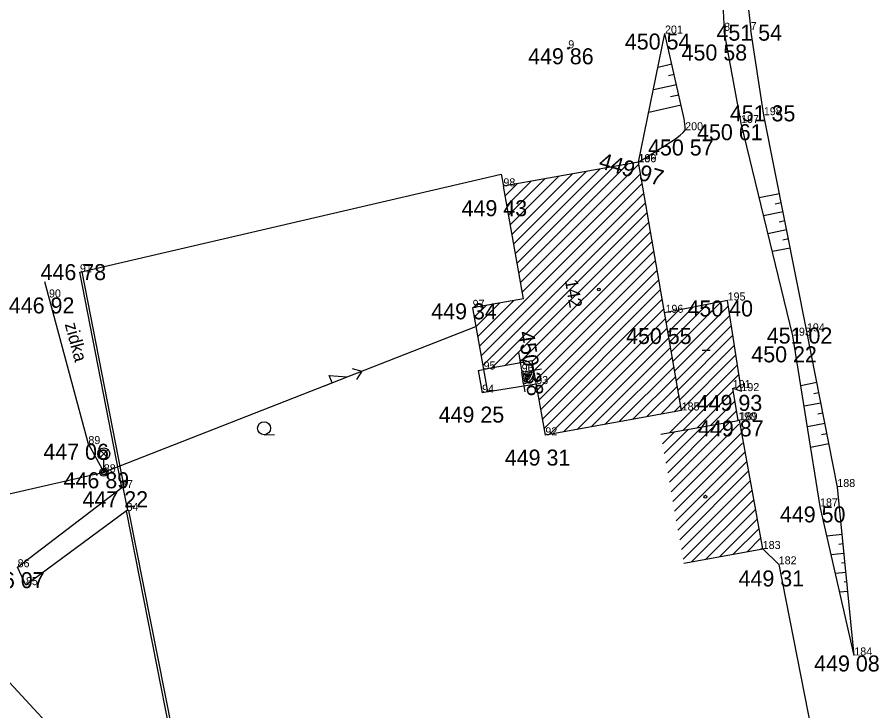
# Model space of a CAD drawing. Extents: x -559180 to -551373, y -1076947 to -1072071.
# Drawn here: x -553839.6 to -553785.8, y -1074531.9 to -1074488.6 of the extents above; entities that cross this region are included whole.
import ezdxf

# ---------------------------------------------------------------- set-up
doc = ezdxf.new("R2010")
doc.units = 0
for name, color, linetype in [('12_PLOTY', 7, 'Continuous'), ('14_BUDOVY', 7, 'Continuous'), ('17_KOMUNIKACE', 7, 'Continuous'), ('18_POLOHOPIS', 7, 'Continuous'), ('1_VODA_ZN', 7, 'Continuous'), ('20_EL_ZN', 7, 'Continuous'), ('26_SRAFY', 7, 'Continuous'), ('27_HRANA_PATA', 7, 'Continuous'), ('32', 7, 'Continuous'), ('3_BODY', 7, 'Continuous'), ('45_ZN_KULTURY', 7, 'Continuous'), ('47_ZN_STAV_OBJ$', 7, 'Continuous'), ('52_POPIS_UCELOVY', 7, 'Continuous'), ('54_C_POPISNA', 7, 'Continuous'), ('6_VYSKY', 7, 'Continuous'), ('NNnadzemní', 7, 'Continuous')]:
    doc.layers.add(name, color=color, linetype=linetype)

# ---------------------------------------------------------------- blocks, each defined once
blk = doc.blocks.new('POINT_DISPLAY')
blk.add_line((0, 0), (0, 0))
blk = doc.blocks.new('SLB')
at = {"layer": '20_EL_ZN'}
for radius in [0.25, 0.158, 0.05]:
    blk.add_circle((0, 0), radius, dxfattribs=at)
blk = doc.blocks.new('LAO')
at = {"layer": '20_EL_ZN'}
for p, q in [((-0.265, 1.415), (0.265, 0.885)), ((-0.265, 0.885), (0.265, 1.415)), ((0, 0), (0, 0.775))]:
    blk.add_line(p, q, dxfattribs=at)
blk.add_circle((0, 1.15), 0.375, dxfattribs=at)
blk = doc.blocks.new('VVH')
at = {"layer": '47_ZN_STAV_OBJ$'}
for p, q in [((-0.001, 0.746), (0, 1.246)), ((0, -0.004), (-0.001, 0.746)), ((0.1, 0.096), (0.099, 0.646)), ((0.099, 0.646), (0.5, 0.396)), ((0, -0.004), (0, 0)), ((0.1, 0.096), (0.2, 0.196)), ((0.65, 0.096), (0.1, 0.096)), ((0.399, 0.346), (0.199, 0.496)), ((0.199, 0.496), (0.2, 0.196)), ((0.2, 0.196), (0.35, 0.346)), ((0.2, 0.196), (0.5, 0.196)), ((0.5, 0.196), (0.399, 0.346)), ((0.5, 0.396), (0.65, 0.096)), ((-1.251, -0.004), (-0.751, -0.004)), ((-0.751, -0.004), (0, -0.004)), ((0.75, -0.004), (0, -0.004)), ((0.75, -0.004), (1.25, -0.004))]:
    blk.add_line(p, q, dxfattribs=at)
for start, end in [(89.9999, 179.9999), (359.9999, 89.9999)]:
    blk.add_arc((0, -0.004), 0.75, start, end, dxfattribs=at)
blk = doc.blocks.new('BZ')
at = {"layer": '47_ZN_STAV_OBJ$'}
blk.add_circle((0, 0), 0.0875, dxfattribs=at)
blk = doc.blocks.new('BD')
at = {"layer": '47_ZN_STAV_OBJ$'}
blk.add_line((-0.25, 0), (0.25, 0), dxfattribs=at)
blk = doc.blocks.new('ZAHRAD')
at = {"layer": '45_ZN_KULTURY'}
blk.add_line((0, 0), (0.65, 0.003), dxfattribs=at)
blk.add_circle((0, 0.403), 0.403, dxfattribs=at)
blk = doc.blocks.new('T')
at = {"layer": '6_VYSKY'}
blk.add_circle((0, 0), 0.05, dxfattribs=at)
blk = doc.blocks.new('ELNN')
at = {"layer": '20_EL_ZN'}
for p, q in [((0, 0), (0.5, 0)), ((0.5, 0), (0.5, 0.5)), ((0.5, 0.5), (1.5, 0)), ((1.5, 0), (2.5, 0))]:
    blk.add_line(p, q, dxfattribs=at)
blk.add_lwpolyline([(2, 0.375), (2.5, 0), (2, -0.375)], dxfattribs=at)

msp = doc.modelspace()

# ---------------------------------------------------------------- linework, layer by layer
at = {"layer": '12_PLOTY'}
for p, q in [((-553835.64, -1074504.56), (-553809.333, -1074498.431)), ((-553809.333, -1074498.431), (-553809.199, -1074499.19)), ((-553833.017, -1074517.99), (-553835.64, -1074504.56)), ((-553832.869, -1074517.961), (-553835.492, -1074504.531)), ((-553832.869, -1074517.961), (-553833.017, -1074517.99)), ((-553832.656, -1074519.446), (-553832.943, -1074517.976)), ((-553832.582, -1074519.431), (-553832.73, -1074519.46)), ((-553829.7, -1074534.8), (-553832.73, -1074519.46)), ((-553829.552, -1074534.77), (-553832.582, -1074519.43)), ((-553792.01, -1074522.8), (-553793.01, -1074521.84)), ((-553792.01, -1074522.8), (-553789.43, -1074535.85))]:
    msp.add_line(p, q, dxfattribs=at)
at = {"layer": '14_BUDOVY'}
for p, q in [((-553800.77, -1074497.69), (-553809.199, -1074499.19)), ((-553798.07, -1074513.19), (-553800.77, -1074497.69)), ((-553807.949, -1074506.216), (-553809.199, -1074499.19)), ((-553807.949, -1074506.216), (-553811.12, -1074506.78)), ((-553795.2, -1074506.32), (-553799.131, -1074507.1)), ((-553794.34, -1074511.98), (-553795.2, -1074506.32)), ((-553811.12, -1074506.78), (-553810.44, -1074510.63)), ((-553807.407, -1074510.095), (-553810.44, -1074510.63)), ((-553806.58, -1074514.74), (-553807.407, -1074510.095)), ((-553794.54, -1074513.81), (-553794.88, -1074511.79)), ((-553794.88, -1074511.79), (-553794.34, -1074511.98)), ((-553798.07, -1074513.19), (-553806.58, -1074514.74)), ((-553799.372, -1074514.675), (-553794.54, -1074513.81)), ((-553794.45, -1074513.8), (-553794.54, -1074513.81)), ((-553793.01, -1074521.84), (-553794.45, -1074513.8)), ((-553797.932, -1074522.721), (-553793.01, -1074521.84))]:
    msp.add_line(p, q, dxfattribs=at)
at = {"layer": '17_KOMUNIKACE'}
msp.add_line((-553842.61, -1074527.4), (-553837.01, -1074533.45), dxfattribs=at)
at = {"layer": '18_POLOHOPIS'}
for p, q in [((-553835.11, -1074515.29), (-553837.829, -1074505.164)), ((-553810.776, -1074510.689), (-553810.44, -1074510.63)), ((-553810.776, -1074510.689), (-553810.53, -1074512.08)), ((-553810.44, -1074510.63), (-553810.193, -1074512.026)), ((-553807.15, -1074511.54), (-553810.53, -1074512.08)), ((-553839.53, -1074522.98), (-553833.017, -1074517.99)), ((-553832.73, -1074519.46), (-553839.01, -1074524.1)), ((-553839.01, -1074524.1), (-553839.53, -1074522.98))]:
    msp.add_line(p, q, dxfattribs=at)
at = {"layer": '26_SRAFY'}
for p, q in [((-553799.539, -1074491.74), (-553798.684, -1074491.548)), ((-553798.883, -1074492.265), (-553798.54, -1074492.188)), ((-553799.829, -1074493.15), (-553798.396, -1074492.829)), ((-553798.769, -1074493.585), (-553798.253, -1074493.469)), ((-553800.119, -1074494.56), (-553798.109, -1074494.109)), ((-553793.225, -1074499.892), (-553791.965, -1074499.641)), ((-553792.224, -1074500.279), (-553791.853, -1074500.205)), ((-553792.952, -1074501.01), (-553791.741, -1074500.768)), ((-553791.985, -1074501.403), (-553791.628, -1074501.332)), ((-553792.68, -1074502.127), (-553791.516, -1074501.896)), ((-553791.746, -1074502.527), (-553791.404, -1074502.459)), ((-553792.407, -1074503.245), (-553791.292, -1074503.023)), ((-553790.628, -1074511.624), (-553789.629, -1074511.429)), ((-553789.811, -1074512.126), (-553789.504, -1074512.067)), ((-553790.424, -1074512.909), (-553789.379, -1074512.704)), ((-553789.575, -1074513.405), (-553789.255, -1074513.342)), ((-553790.221, -1074514.193), (-553789.13, -1074513.98)), ((-553789.339, -1074514.683), (-553789.005, -1074514.618)), ((-553790.017, -1074515.478), (-553788.881, -1074515.256)), ((-553789.009, -1074521.011), (-553788.053, -1074520.915)), ((-553788.258, -1074521.533), (-553787.994, -1074521.507)), ((-553788.74, -1074522.18), (-553787.934, -1074522.099)), ((-553788.094, -1074522.713), (-553787.874, -1074522.691)), ((-553788.472, -1074523.349), (-553787.815, -1074523.283)), ((-553787.93, -1074523.892), (-553787.755, -1074523.875)), ((-553788.203, -1074524.518), (-553787.695, -1074524.467))]:
    msp.add_line(p, q, dxfattribs=at)
at = {"layer": '27_HRANA_PATA'}
for p, q in [((-553794.61, -1074481.81), (-553793.76, -1074489.43)), ((-553795.74, -1074482.18), (-553795.42, -1074489.48)), ((-553794.36, -1074495.24), (-553795.42, -1074489.48)), ((-553792.94, -1074494.75), (-553793.76, -1074489.43)), ((-553800.76, -1074497.68), (-553799.11, -1074489.65)), ((-553790.25, -1074508.25), (-553792.94, -1074494.75)), ((-553791.12, -1074508.52), (-553794.36, -1074495.24)), ((-553788.35, -1074517.97), (-553790.25, -1074508.25)), ((-553789.43, -1074519.18), (-553791.12, -1074508.52)), ((-553835.11, -1074515.29), (-553834.15, -1074517.05)), ((-553787.29, -1074528.49), (-553788.35, -1074517.97)), ((-553787.29, -1074528.49), (-553789.43, -1074519.18))]:
    msp.add_line(p, q, dxfattribs=at)
for points in [[(-553797.85, -1074495.69), (-553797.849, -1074495.485), (-553797.865, -1074495.308), (-553797.915, -1074494.973), (-553799.11, -1074489.65)], [(-553800.76, -1074497.68), (-553798.58, -1074496.317), (-553798.346, -1074496.143), (-553798.157, -1074495.986), (-553797.98, -1074495.827), (-553797.85, -1074495.69)]]:
    msp.add_lwpolyline(points, dxfattribs=at)
at = {"layer": '32'}
for p, q in [((-553808.451, -1074503.392), (-553803.178, -1074498.118)), ((-553808.345, -1074503.992), (-553802.318, -1074497.965)), ((-553808.238, -1074504.593), (-553801.457, -1074497.812)), ((-553808.131, -1074505.193), (-553800.749, -1074497.811)), ((-553808.772, -1074501.591), (-553805.758, -1074498.578)), ((-553808.665, -1074502.192), (-553804.898, -1074498.425)), ((-553808.558, -1074502.792), (-553804.038, -1074498.272)), ((-553808.024, -1074505.793), (-553800.644, -1074498.413)), ((-553810.697, -1074509.174), (-553800.539, -1074499.015)), ((-553809.092, -1074499.79), (-553808.339, -1074499.037)), ((-553808.985, -1074500.391), (-553807.479, -1074498.884)), ((-553808.879, -1074500.991), (-553806.618, -1074498.731)), ((-553810.591, -1074509.774), (-553800.434, -1074499.618)), ((-553810.485, -1074510.375), (-553800.329, -1074500.22)), ((-553809.945, -1074510.543), (-553800.224, -1074500.822)), ((-553809.087, -1074510.391), (-553800.12, -1074501.424)), ((-553808.228, -1074510.24), (-553800.015, -1074502.026)), ((-553807.402, -1074510.121), (-553799.91, -1074502.629)), ((-553807.295, -1074510.721), (-553799.805, -1074503.231)), ((-553807.189, -1074511.322), (-553799.7, -1074503.833)), ((-553807.082, -1074511.922), (-553799.595, -1074504.435)), ((-553806.975, -1074512.522), (-553799.49, -1074505.037)), ((-553806.868, -1074513.122), (-553799.385, -1074505.64)), ((-553811.016, -1074507.371), (-553810.275, -1074506.63)), ((-553810.91, -1074507.972), (-553809.415, -1074506.477)), ((-553810.803, -1074508.573), (-553808.555, -1074506.324)), ((-553806.761, -1074513.723), (-553799.28, -1074506.242)), ((-553798.816, -1074508.907), (-553796.485, -1074506.575)), ((-553798.711, -1074509.509), (-553795.602, -1074506.4)), ((-553798.606, -1074510.111), (-553795.149, -1074506.654)), ((-553806.654, -1074514.323), (-553799.175, -1074506.844)), ((-553799.026, -1074507.702), (-553798.249, -1074506.925)), ((-553798.921, -1074508.304), (-553797.367, -1074506.75)), ((-553806.316, -1074514.692), (-553799.071, -1074507.446)), ((-553798.502, -1074510.713), (-553795.056, -1074507.268)), ((-553805.452, -1074514.534), (-553798.966, -1074508.048)), ((-553798.397, -1074511.315), (-553794.963, -1074507.881)), ((-553804.587, -1074514.377), (-553798.861, -1074508.651)), ((-553798.292, -1074511.918), (-553794.869, -1074508.495)), ((-553803.722, -1074514.22), (-553798.756, -1074509.253)), ((-553798.187, -1074512.52), (-553794.776, -1074509.109)), ((-553802.858, -1074514.062), (-553798.651, -1074509.855)), ((-553798.082, -1074513.122), (-553794.683, -1074509.723)), ((-553801.993, -1074513.905), (-553798.546, -1074510.457)), ((-553798.831, -1074514.578), (-553794.59, -1074510.337)), ((-553797.97, -1074514.424), (-553794.496, -1074510.951)), ((-553801.129, -1074513.747), (-553798.441, -1074511.06)), ((-553794.694, -1074511.855), (-553794.403, -1074511.565)), ((-553800.264, -1074513.59), (-553798.336, -1074511.662)), ((-553797.108, -1074514.27), (-553794.844, -1074512.005)), ((-553799.4, -1074513.432), (-553798.231, -1074512.264)), ((-553796.247, -1074514.116), (-553794.742, -1074512.61)), ((-553798.535, -1074513.275), (-553798.126, -1074512.866)), ((-553795.386, -1074513.961), (-553794.64, -1074513.216)), ((-553799.05, -1074516.474), (-553796.788, -1074514.212)), ((-553798.943, -1074517.074), (-553795.927, -1074514.058)), ((-553798.835, -1074517.674), (-553795.066, -1074513.904)), ((-553798.728, -1074518.274), (-553794.496, -1074514.042)), ((-553799.265, -1074515.275), (-553798.511, -1074514.521)), ((-553799.157, -1074515.875), (-553797.649, -1074514.367)), ((-553798.621, -1074518.873), (-553794.383, -1074514.635)), ((-553798.513, -1074519.473), (-553794.27, -1074515.229)), ((-553798.406, -1074520.073), (-553794.156, -1074515.823)), ((-553798.299, -1074520.673), (-553794.043, -1074516.417)), ((-553798.191, -1074521.272), (-553793.93, -1074517.011)), ((-553798.084, -1074521.872), (-553793.817, -1074517.605)), ((-553797.977, -1074522.472), (-553793.704, -1074518.199)), ((-553797.428, -1074522.631), (-553793.591, -1074518.793)), ((-553796.567, -1074522.477), (-553793.477, -1074519.387)), ((-553795.706, -1074522.323), (-553793.364, -1074519.981)), ((-553794.845, -1074522.168), (-553793.251, -1074520.575)), ((-553793.983, -1074522.014), (-553793.138, -1074521.169)), ((-553793.122, -1074521.86), (-553793.025, -1074521.763))]:
    msp.add_line(p, q, dxfattribs=at)
at = {"layer": 'NNnadzemní'}
for p, q in [((-553834.15, -1074517.05), (-553810.915, -1074507.941)), ((-553869.639, -1074525.168), (-553834.15, -1074517.05))]:
    msp.add_line(p, q, dxfattribs=at)

# ---------------------------------------------------------------- block references
at = {"layer": '1_VODA_ZN'}
for p in [(-553795.42, -1074489.48), (-553793.76, -1074489.43), (-553799.11, -1074489.65), (-553805.15, -1074490.57), (-553792.94, -1074494.75), (-553794.36, -1074495.24), (-553797.85, -1074495.69), (-553800.77, -1074497.69), (-553800.76, -1074497.68), (-553809.2, -1074499.19), (-553835.64, -1074504.56), (-553792.039, -1074504.633), (-553837.57, -1074506.13), (-553795.2, -1074506.32), (-553811.12, -1074506.78), (-553799.08, -1074507.09), (-553790.25, -1074508.25), (-553791.12, -1074508.52), (-553810.44, -1074510.63), (-553808.06, -1074510.79), (-553807.15, -1074511.54), (-553810.53, -1074512.08), (-553794.88, -1074511.79), (-553794.34, -1074511.98), (-553798.07, -1074513.19), (-553794.54, -1074513.81), (-553794.45, -1074513.8), (-553806.58, -1074514.74), (-553835.11, -1074515.29), (-553834.15, -1074517.05), (-553788.35, -1074517.97), (-553833.07, -1074518.03), (-553832.73, -1074519.46), (-553789.43, -1074519.18), (-553793.01, -1074521.84), (-553792.01, -1074522.8), (-553839.53, -1074522.98), (-553839.01, -1074524.1), (-553787.29, -1074528.49)]:
    msp.add_blockref('POINT_DISPLAY', p, dxfattribs=at)
at = {"layer": '20_EL_ZN', "xscale": 1.0000008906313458, "yscale": 1.0000008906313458, "rotation": 21.40698381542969}
msp.add_blockref('ELNN', (-553820.36, -1074511.644), dxfattribs=at)
at = {"layer": '20_EL_ZN'}
for name in ['LAO', 'SLB']:
    msp.add_blockref(name, (-553834.15, -1074517.05), dxfattribs=at)
at = {"layer": '32'}
for p in [(-553809.199, -1074499.19), (-553799.131, -1074507.1), (-553799.372, -1074514.675)]:
    msp.add_blockref('POINT_DISPLAY', p, dxfattribs=at)
at = {"layer": '45_ZN_KULTURY'}
msp.add_blockref('ZAHRAD', (-553824.141, -1074514.701), dxfattribs=at)
at = {"layer": '47_ZN_STAV_OBJ$'}
for name, p in [('BZ', (-553803.246, -1074505.631)), ('BD', (-553796.535, -1074509.422)), ('BZ', (-553796.589, -1074518.575))]:
    msp.add_blockref(name, p, dxfattribs=at)
at = {"layer": '47_ZN_STAV_OBJ$', "xscale": 1.0000016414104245, "yscale": 1.0000016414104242, "rotation": -81.01973074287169}
msp.add_blockref('VVH', (-553808.052, -1074510.789), dxfattribs=at)
at = {"layer": '6_VYSKY'}
msp.add_blockref('T', (-553805.15, -1074490.57), dxfattribs=at)
msp.add_blockref('T', (-553805.15, -1074490.57), dxfattribs=at)

# ---------------------------------------------------------------- texts
at = {"layer": '3_BODY'}
for s, p in [('8', (-553795.42, -1074489.48)), ('7', (-553793.76, -1074489.43)), ('201', (-553799.11, -1074489.65)), ('9', (-553805.15, -1074490.57)), ('198', (-553792.94, -1074494.75)), ('197', (-553794.36, -1074495.24)), ('200', (-553797.85, -1074495.69)), ('186', (-553800.77, -1074497.69)), ('199', (-553800.76, -1074497.68)), ('98', (-553809.2, -1074499.19)), ('91', (-553835.64, -1074504.56)), ('90', (-553837.57, -1074506.13)), ('195', (-553795.2, -1074506.32)), ('97', (-553811.12, -1074506.78)), ('196', (-553799.08, -1074507.09)), ('194', (-553790.25, -1074508.25)), ('193', (-553791.12, -1074508.52)), ('95', (-553810.44, -1074510.63)), ('96', (-553808.06, -1074510.79)), ('93', (-553807.15, -1074511.54)), ('191', (-553794.88, -1074511.79)), ('192', (-553794.34, -1074511.98)), ('94', (-553810.53, -1074512.08)), ('185', (-553798.07, -1074513.19)), ('190', (-553794.54, -1074513.81)), ('189', (-553794.45, -1074513.8)), ('92', (-553806.58, -1074514.74)), ('89', (-553835.11, -1074515.29)), ('88', (-553834.15, -1074517.05)), ('188', (-553788.35, -1074517.97)), ('87', (-553833.07, -1074518.03)), ('84', (-553832.73, -1074519.46)), ('187', (-553789.43, -1074519.18)), ('183', (-553793.01, -1074521.84)), ('182', (-553792.01, -1074522.8)), ('86', (-553839.53, -1074522.98)), ('85', (-553839.01, -1074524.1)), ('184', (-553787.29, -1074528.49))]:
    msp.add_text(s, height=0.5, dxfattribs=at).set_placement(p)
at = {"layer": '52_POPIS_UCELOVY'}
msp.add_text('zidka', height=0.8, rotation=285.0303, dxfattribs=at).set_placement((-553836.591, -1074507.803))
at = {"layer": '54_C_POPISNA'}
msp.add_text('142', height=0.8, rotation=280.0163, dxfattribs=at).set_placement((-553805.363, -1074505.068))
at = {"layer": '6_VYSKY'}
for s, p in [('451 54', (-553795.894, -1074490.096)), ('450 54', (-553801.615, -1074490.65)), ('449 86', (-553807.655, -1074491.57)), ('450 58', (-553798.073, -1074491.334)), ('451 35', (-553795.059, -1074495.133)), ('450 61', (-553797.108, -1074496.31)), ('450 57', (-553800.165, -1074497.266)), ('449 43', (-553811.807, -1074501.057)), ('446 78', (-553838.094, -1074505.05)), ('446 92', (-553840.075, -1074507.13)), ('449 34', (-553813.702, -1074507.499)), ('450 40', (-553797.705, -1074507.32)), ('450 55', (-553801.538, -1074509.039)), ('451 02', (-553792.755, -1074509.012)), ('450 22', (-553793.72, -1074510.184)), ('449 93', (-553797.129, -1074513.217)), ('449 25', (-553813.239, -1074513.947)), ('449 87', (-553797.045, -1074514.81)), ('447 06', (-553837.921, -1074516.265)), ('449 31', (-553809.111, -1074516.632)), ('446 89', (-553836.655, -1074518.05)), ('447 22', (-553835.473, -1074519.234)), ('449 50', (-553791.935, -1074520.18)), ('446 07', (-553841.933, -1074524.286)), ('449 31', (-553794.515, -1074524.179)), ('449 08', (-553789.795, -1074529.49))]:
    msp.add_text(s, height=1, dxfattribs=at).set_placement(p)
for s, rotation, p in [('449 97', 343.5206, (-553803.305, -1074498.026)), ('450 38', 278.7362, (-553808.285, -1074508.3))]:
    msp.add_text(s, height=1, rotation=rotation, dxfattribs=at).set_placement(p)

doc.saveas('drawing.dxf')
